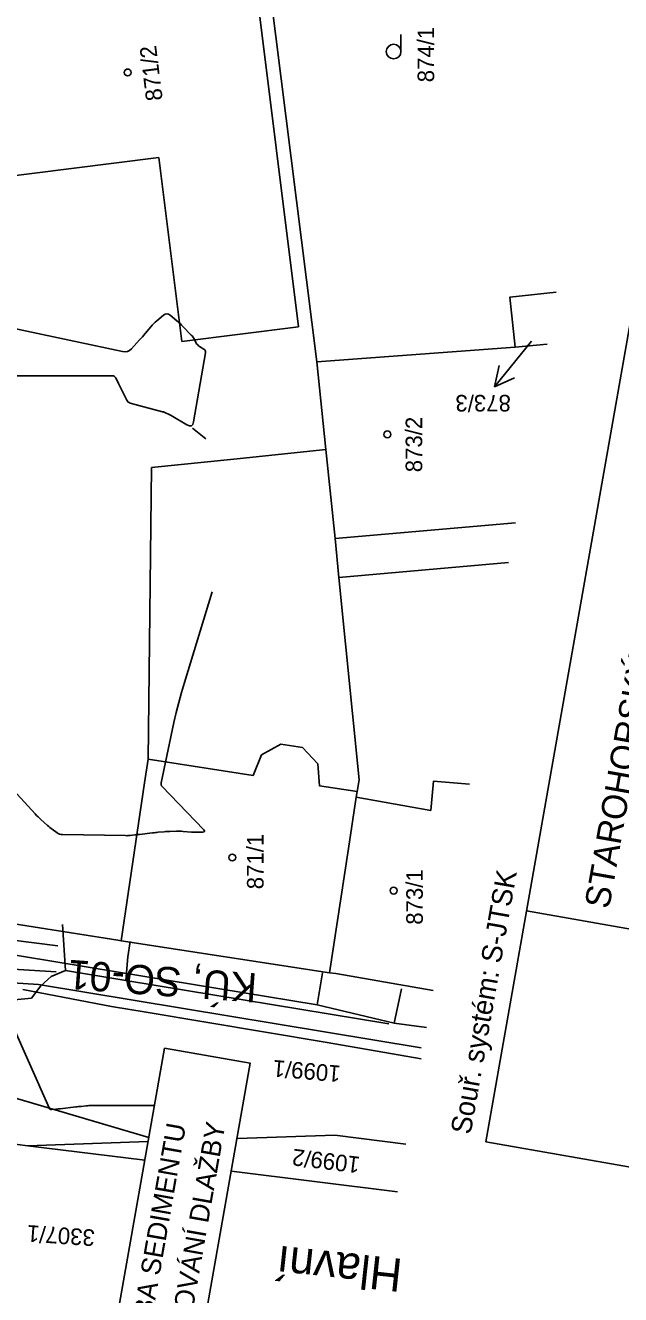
# Model space of a CAD drawing. Extents: x -534481 to -534262, y -1190577 to -1190138.
# Drawn here: x -534337 to -534306.5, y -1190251.9 to -1190186.9 of the extents above; entities that cross this region are included whole.
import ezdxf

# ---------------------------------------------------------------- set-up
doc = ezdxf.new("R2010")
doc.units = 0
for name, color, linetype in [('14', 7, 'Continuous'), ('Definiční body', 7, 'Continuous'), ('Level 30', 7, 'Continuous'), ('Polygon budovy', 7, 'Continuous'), ('Polygon parcely', 7, 'Continuous'), ('Vrstva 1', 7, 'Continuous'), ('Vrstva 18', 7, 'Continuous'), ('Vrstva 19', 7, 'Continuous'), ('Vrstva 31', 7, 'Continuous'), ('Vrstva 32', 7, 'Continuous'), ('Vrstva 35', 7, 'Continuous'), ('Vrstva 42', 7, 'Continuous'), ('Vrstva 46', 7, 'Continuous'), ('Vrstva 47', 7, 'Continuous'), ('Vrstva 48', 7, 'Continuous'), ('Vrstva 58', 7, 'Continuous')]:
    doc.layers.add(name, color=color, linetype=linetype)

msp = doc.modelspace()

# ---------------------------------------------------------------- linework, layer by layer
at = {"layer": '14'}
for points in [[(-534316.429, -1190238.25), (-534318.08, -1190238.03), (-534322.04, -1190237.08), (-534332.22, -1190235.41), (-534338.777, -1190234.334), (-534339.342, -1190238.274), (-534345.981, -1190237.953), (-534362.202, -1190237.552), (-534365.29, -1190237.5)], [(-534322.04, -1190237.08), (-534321.76, -1190235.45)], [(-534318.08, -1190238.03), (-534317.71, -1190236.27)]]:
    msp.add_lwpolyline(points, dxfattribs=at)
at = {"layer": 'Definiční body'}
for p, q in [((-534322.05, -1190204.13), (-534324.69, -1190183.16)), ((-534322.05, -1190204.13), (-534311.89, -1190203.37)), ((-534311.89, -1190203.37), (-534310.251, -1190203.215)), ((-534321.59, -1190208.63), (-534322.05, -1190204.13)), ((-534312.226, -1190214.415), (-534320.92, -1190215.18)), ((-534332.08, -1190233.8), (-534321.41, -1190235.44)), ((-534339.93, -1190243.93), (-534336.87, -1190244.31)), ((-534336.87, -1190244.31), (-534330.88, -1190245.056)), ((-534326.423, -1190245.612), (-534317.914, -1190246.672))]:
    msp.add_line(p, q, dxfattribs=at)
for points in [[(-534311.89, -1190203.37), (-534312.15, -1190200.81), (-534309.784, -1190200.563)], [(-534321.59, -1190208.63), (-534326.31, -1190209.11), (-534330.53, -1190209.55), (-534330.71, -1190224.5), (-534330.89, -1190225.71), (-534332.08, -1190233.8)], [(-534320.92, -1190215.18), (-534321.12, -1190213.19), (-534321.59, -1190208.63)], [(-534321.41, -1190235.44), (-534320.43, -1190229.08), (-534320.03, -1190226.45), (-534319.98, -1190226.15), (-534319.89, -1190225.56), (-534320.92, -1190215.18)], [(-534340.96, -1190232.41), (-534332.26, -1190233.77), (-534332.08, -1190233.8)], [(-534316.094, -1190236.35), (-534321.08, -1190235.49), (-534321.41, -1190235.44)], [(-534336.87, -1190244.31), (-534330.711, -1190244.099)], [(-534326.128, -1190243.941), (-534321.13, -1190243.77), (-534317.482, -1190244.222)]]:
    msp.add_lwpolyline(points, dxfattribs=at)
at = {"layer": 'Level 30'}
for p, q in [((-534335.1, -1190232.971), (-534334.95, -1190235.33)), ((-534331.75, -1190234.62), (-534331.622, -1190233.843)), ((-534331.85, -1190235.84), (-534331.75, -1190234.62)), ((-534336.21, -1190236.11), (-534335.67, -1190235.64)), ((-534335.67, -1190235.64), (-534334.95, -1190235.33)), ((-534334.95, -1190235.33), (-534331.85, -1190235.84)), ((-534331.85, -1190235.84), (-534318.36, -1190238.06)), ((-534336.69, -1190236.75), (-534336.21, -1190236.11)), ((-534337.56, -1190236.84), (-534336.69, -1190236.75)), ((-534318.36, -1190238.06), (-534318.36, -1190238.06)), ((-534318.36, -1190238.06), (-534318.36, -1190238.06))]:
    msp.add_line(p, q, dxfattribs=at)
at = {"layer": 'Polygon parcely'}
for points in [[(-534325.28, -1190183.96), (-534342.24, -1190186.06), (-534341.16, -1190195.04), (-534330.16, -1190193.66), (-534328.97, -1190203.08), (-534323, -1190202.33)], [(-534330.71, -1190224.5), (-534330.89, -1190225.71), (-534332.08, -1190233.8), (-534321.41, -1190235.44), (-534320.43, -1190229.08), (-534320.03, -1190226.45), (-534319.98, -1190226.15), (-534321.92, -1190225.86), (-534322.01, -1190224.729), (-534322.782, -1190223.898), (-534323.902, -1190223.723), (-534324.89, -1190224.281), (-534325.32, -1190225.33)]]:
    msp.add_lwpolyline(points, close=True, dxfattribs=at)
for points in [[(-534310.251, -1190203.215), (-534311.89, -1190203.37), (-534322.05, -1190204.13), (-534321.59, -1190208.63), (-534321.12, -1190213.19), (-534311.868, -1190212.381)], [(-534314.231, -1190225.785), (-534316.08, -1190225.63), (-534316.21, -1190227.12), (-534320.03, -1190226.45), (-534320.43, -1190229.08), (-534321.41, -1190235.44), (-534321.08, -1190235.49), (-534316.094, -1190236.35)]]:
    msp.add_lwpolyline(points, dxfattribs=at)
at = {"layer": 'Vrstva 1'}
for points in [[(-534337.129, -1190236.298), (-534332.576, -1190237.179), (-534330.798, -1190237.457)], [(-534316.712, -1190239.853), (-534318.166, -1190239.603), (-534321.619, -1190239.01), (-534330.798, -1190237.457)], [(-534316.712, -1190239.853), (-534318.166, -1190239.603)]]:
    msp.add_lwpolyline(points, dxfattribs=at)
at = {"layer": 'Vrstva 18'}
msp.add_lwpolyline([(-534339.697, -1190233.583), (-534335.786, -1190242.375), (-534335.761, -1190242.416), (-534335.728, -1190242.444), (-534335.687, -1190242.459), (-534335.639, -1190242.46), (-534335.43, -1190242.438), (-534335.378, -1190242.433), (-534335.326, -1190242.427), (-534335.274, -1190242.421), (-534335.222, -1190242.415), (-534334.417, -1190242.321), (-534334.349, -1190242.313), (-534334.282, -1190242.306), (-534334.215, -1190242.299), (-534334.147, -1190242.292), (-534333.878, -1190242.264), (-534333.81, -1190242.258), (-534333.743, -1190242.254), (-534333.675, -1190242.252), (-534333.608, -1190242.251), (-534330.385, -1190242.251)], dxfattribs=at)
at = {"layer": 'Vrstva 19'}
for points in [[(-534337.735, -1190202.39), (-534332.013, -1190203.605), (-534331.884, -1190203.618), (-534331.764, -1190203.597), (-534331.655, -1190203.544), (-534331.557, -1190203.458), (-534331.149, -1190203.009), (-534331.075, -1190202.927), (-534331.001, -1190202.843), (-534330.928, -1190202.759), (-534330.855, -1190202.675), (-534330.567, -1190202.335), (-534330.493, -1190202.251), (-534330.416, -1190202.171), (-534330.336, -1190202.094), (-534330.253, -1190202.021), (-534329.913, -1190201.732), (-534329.828, -1190201.678), (-534329.743, -1190201.66), (-534329.658, -1190201.678), (-534329.573, -1190201.732), (-534329.234, -1190202.021), (-534329.15, -1190202.094), (-534329.068, -1190202.17), (-534328.988, -1190202.247), (-534328.91, -1190202.326), (-534328.496, -1190202.756), (-534328.455, -1190202.801), (-534328.417, -1190202.849), (-534328.383, -1190202.9), (-534328.352, -1190202.953), (-534328.234, -1190203.169), (-534328.202, -1190203.22), (-534328.164, -1190203.265), (-534328.12, -1190203.306), (-534328.07, -1190203.34), (-534327.851, -1190203.472), (-534327.805, -1190203.508), (-534327.775, -1190203.552), (-534327.762, -1190203.603), (-534327.764, -1190203.662), (-534328.372, -1190207.198), (-534328.415, -1190207.333), (-534328.488, -1190207.405), (-534328.59, -1190207.413), (-534328.72, -1190207.359), (-534329.524, -1190206.885), (-534329.559, -1190206.865), (-534329.594, -1190206.846), (-534329.63, -1190206.827), (-534329.666, -1190206.809), (-534329.811, -1190206.739), (-534329.848, -1190206.722), (-534329.885, -1190206.708), (-534329.923, -1190206.695), (-534329.961, -1190206.683), (-534331.178, -1190206.359), (-534331.366, -1190206.309), (-534331.618, -1190206.242), (-534331.676, -1190206.22), (-534331.726, -1190206.188), (-534331.767, -1190206.145), (-534331.8, -1190206.092), (-534332.219, -1190205.237), (-534332.357, -1190204.957), (-534332.389, -1190204.908), (-534332.429, -1190204.873), (-534332.479, -1190204.852), (-534332.537, -1190204.845), (-534337.626, -1190204.845)], [(-534327.743, -1190208.078), (-534328.429, -1190207.531)], [(-534338.173, -1190225.473), (-534336.493, -1190227.306), (-534336.423, -1190227.381), (-534336.352, -1190227.453), (-534336.278, -1190227.523), (-534336.202, -1190227.592), (-534335.857, -1190227.896), (-534335.799, -1190227.946), (-534335.741, -1190227.994), (-534335.682, -1190228.041), (-534335.621, -1190228.087), (-534335.377, -1190228.267), (-534335.314, -1190228.306), (-534335.248, -1190228.335), (-534335.177, -1190228.352), (-534335.104, -1190228.359), (-534331.863, -1190228.416), (-534331.803, -1190228.417), (-534331.743, -1190228.415), (-534331.684, -1190228.411), (-534331.624, -1190228.406), (-534331.386, -1190228.381), (-534331.327, -1190228.375), (-534331.267, -1190228.368), (-534331.208, -1190228.362), (-534331.149, -1190228.355), (-534330.475, -1190228.276), (-534330.402, -1190228.267), (-534330.329, -1190228.259), (-534330.256, -1190228.251), (-534330.182, -1190228.244), (-534329.89, -1190228.214), (-534329.816, -1190228.207), (-534329.743, -1190228.202), (-534329.669, -1190228.198), (-534329.596, -1190228.195), (-534329.246, -1190228.186), (-534329.163, -1190228.185), (-534329.081, -1190228.187), (-534328.998, -1190228.19), (-534328.915, -1190228.196), (-534328.489, -1190228.234), (-534328.414, -1190228.24), (-534328.34, -1190228.243), (-534328.265, -1190228.244), (-534328.191, -1190228.243), (-534327.892, -1190228.233), (-534327.834, -1190228.224), (-534327.806, -1190228.202), (-534327.811, -1190228.168), (-534327.847, -1190228.12), (-534330.005, -1190225.88), (-534330.014, -1190225.868), (-534330.022, -1190225.856), (-534330.027, -1190225.842), (-534330.03, -1190225.828), (-534330.04, -1190225.768), (-534330.041, -1190225.753), (-534330.042, -1190225.738), (-534330.04, -1190225.723), (-534330.038, -1190225.708), (-534329.379, -1190222.622), (-534329.262, -1190222.105), (-534329.134, -1190221.59), (-534328.995, -1190221.078), (-534328.845, -1190220.569), (-534327.417, -1190215.923)]]:
    msp.add_lwpolyline(points, dxfattribs=at)
at = {"layer": 'Vrstva 31'}
msp.add_lwpolyline([(-534329.865, -1190239.303), (-534335.236, -1190269.762), (-534330.848, -1190270.536), (-534325.477, -1190240.077)], close=True, dxfattribs=at)
msp.add_lwpolyline([(-534330.674, -1190243.891), (-534342.784, -1190240.314), (-534341.716, -1190241.248)], dxfattribs=at)
at = {"layer": 'Vrstva 32'}
msp.add_line((-534335.423, -1190235.405), (-534349.394, -1190234.5), dxfattribs=at)
at = {"layer": 'Vrstva 35'}
msp.add_lwpolyline([(-534366.521, -1190234.728), (-534348.981, -1190235.231), (-534336.32, -1190236.042), (-534316.711, -1190239.297)], dxfattribs=at)
at = {"layer": 'Vrstva 42'}
for p, q in [((-534313.394, -1190244.109), (-534298.633, -1190160.401)), ((-534278.064, -1190238.127), (-534311.305, -1190232.266)), ((-534280.153, -1190249.971), (-534313.394, -1190244.109))]:
    msp.add_line(p, q, dxfattribs=at)
at = {"layer": 'Vrstva 46'}
for centre in [(-534331.751, -1190189.294), (-534318.435, -1190207.847), (-534326.391, -1190229.536), (-534318.117, -1190231.234)]:
    msp.add_circle(centre, 0.175, dxfattribs=at)
at = {"layer": 'Vrstva 47'}
for p, q in [((-534311.051, -1190203.076), (-534312.94, -1190205.408)), ((-534312.94, -1190205.408), (-534312.698, -1190204.315)), ((-534312.94, -1190205.408), (-534311.92, -1190204.945))]:
    msp.add_line(p, q, dxfattribs=at)
at = {"layer": 'Vrstva 48'}
msp.add_line((-534317.741, -1190188.223), (-534317.741, -1190187.348), dxfattribs=at)
msp.add_circle((-534318.117, -1190188.223), 0.375, dxfattribs=at)
at = {"layer": 'Vrstva 58'}
msp.add_lwpolyline([(-534349.315, -1190233.89), (-534345.01, -1190233.79), (-534342.01, -1190233.7), (-534339, -1190233.61), (-534335.33, -1190234.069)], dxfattribs=at)

# ---------------------------------------------------------------- texts
at = {"layer": 'Polygon budovy'}
for s, rotation, p in [('874/1', 90, (-534316.038, -1190189.799)), ('871/2', 97, (-534329.954, -1190190.7)), ('873/3', 180, (-534312.104, -1190205.824)), ('873/2', 90, (-534316.651, -1190209.788)), ('871/1', 90, (-534324.784, -1190231.164)), ('873/1', 90, (-534316.619, -1190232.982)), ('1099/1', 175, (-534320.803, -1190240.214)), ('1099/2', 173, (-534319.805, -1190244.888)), ('3307/1', 176, (-534333.411, -1190248.616))]:
    msp.add_text(s, height=0.85, rotation=rotation, dxfattribs=at).set_placement(p)
at = {"layer": 'Vrstva 31'}
for s, height, rotation, p in [('KÚ, SO-01', 1.5, 175.83222, (-534325.077, -1190235.481)), ('OBJEM 9,7 m³ + PŘESPÁROVÁNÍ DLAŽBY', 1, 80.02054, (-534331.31, -1190269.211)), ('Ř. KM 0,3225 - 0,330: TĚŽBA SEDIMENTU ', 1, 80.02054, (-534333.264, -1190268.867))]:
    msp.add_text(s, height=height, rotation=rotation, dxfattribs=at).set_placement(p)
at = {"layer": 'Vrstva 42'}
for s, height, p in [('STAROHORSKÝ POTOK, HLUK - ŘKM 0,000 ', 1.2825, (-534307.068, -1190232.21)), ('Souř. systém: S-JTSK', 1.04194, (-534314.172, -1190243.775))]:
    msp.add_text(s, height=height, rotation=80, dxfattribs=at).set_placement(p)
at = {"layer": 'Vrstva 47'}
msp.add_text('Hlavní', height=1.7, rotation=173.78778, dxfattribs=at).set_placement((-534317.605, -1190250.124))

doc.saveas('drawing.dxf')
